(* Logix 5000 project; controller logix5561 vendor 1 type 14 code 54 rev 19.11; software revision 19.01 *)

TASK MainTask (continuous, watchdog 500 ms) : MainProgram

MODULES
   Local : vendor 1 type 14 code 54 (ICP 0, rev 19.11)
      EIP : 1756-ENBT (ICP 1, Ethernet 192.168.16.199, rev 6.1)
         Fuji_Inverter : ETHERNET-MODULE (Ethernet 192.168.16.28, rev 1.1, Output RPI 10 ms)
END_MODULES

ADD_ON_INSTRUCTION OPCE1WIE_Generic_Default_IO   (* revision 1.0 *)
// Simple interface for generic default IO mapping that uses Input Assembly Instance 150 and Output Assembly Instance 100.
VAR_IN_OUT
   I_Data : INT[2]; {required}   // Input data
   O_Data : INT[2]; {required}   // Output data
END_VAR
VAR_INPUT
   RunForward : BOOL; {access Read Only, required}   // Run Forward
   RunReverse : BOOL; {access Read Only, required}   // Run reverse
   ResetFault : BOOL; {access Read Only, required}   // Reset fault
   FrequencyCommand : INT; {access Read Only, required}   // Frequency command/reference
END_VAR
VAR_OUTPUT
   RunningForward : BOOL; {access Read Only, visible}   // Running forward
   RunningReverse : BOOL; {access Read Only, visible}   // Running reverse
   DCBreaking : BOOL; {access Read Only, visible}   // DC injection braking (or pre-exciting)
   InverterShutdown : BOOL; {access Read Only, visible}   // Inverter shutdown (stopped)
   Braking : BOOL; {access Read Only, visible}   // Braking
   DCBusVoltageNormal : BOOL; {access Read Only, visible}   // DC bus voltage normal
   TorqueLimiting : BOOL; {access Read Only, visible}   // Torque limited
   VoltageLimited : BOOL; {access Read Only, visible}   // Voltage limited
   CurrentLimited : BOOL; {access Read Only, visible}   // Current limited
   Accelerating : BOOL; {access Read Only, visible}   // Accelerating
   Decelerating : BOOL; {access Read Only, visible}   // Decelerating
   Alarm : BOOL; {access Read Only, visible}   // Alarm relay (for any fault)
   CommEstablished : BOOL; {access Read Only, visible}   // Communications established
   BusyWriting : BOOL; {access Read Only, visible}   // Write in progress
   OutputFrequency : INT; {access Read Only, visible}   // Output/feedback frequency
END_VAR

ROUTINE Logic   (* ladder *)
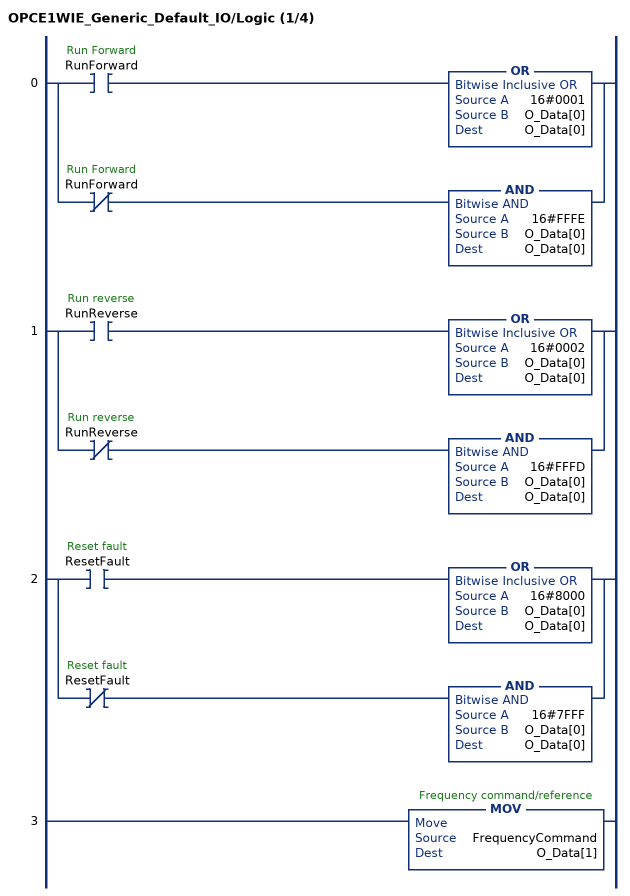
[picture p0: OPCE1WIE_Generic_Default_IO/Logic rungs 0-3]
   0: [XIC(RunForward) OR(16#0001,O_Data[0],O_Data[0]) ,XIO(RunForward) AND(16#FFFE,O_Data[0],O_Data[0]) ];
   1: [XIC(RunReverse) OR(16#0002,O_Data[0],O_Data[0]) ,XIO(RunReverse) AND(16#FFFD,O_Data[0],O_Data[0]) ];
   2: [XIC(ResetFault) OR(16#8000,O_Data[0],O_Data[0]) ,XIO(ResetFault) AND(16#7FFF,O_Data[0],O_Data[0]) ];
   3: MOV(FrequencyCommand,O_Data[1]);
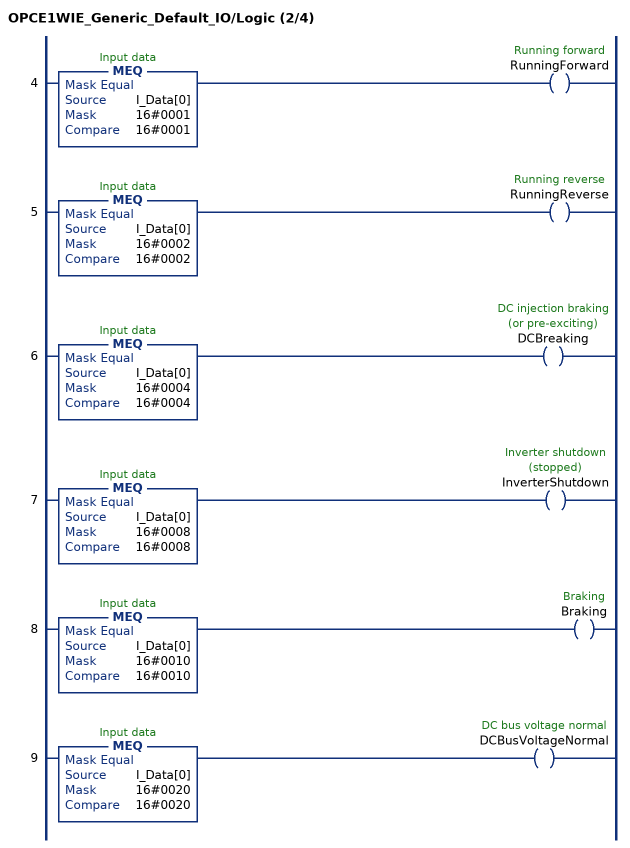
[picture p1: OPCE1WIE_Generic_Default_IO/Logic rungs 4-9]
   4: MEQ(I_Data[0],16#0001,16#0001)OTE(RunningForward);
   5: MEQ(I_Data[0],16#0002,16#0002)OTE(RunningReverse);
   6: MEQ(I_Data[0],16#0004,16#0004)OTE(DCBreaking);
   7: MEQ(I_Data[0],16#0008,16#0008)OTE(InverterShutdown);
   8: MEQ(I_Data[0],16#0010,16#0010)OTE(Braking);
   9: MEQ(I_Data[0],16#0020,16#0020)OTE(DCBusVoltageNormal);
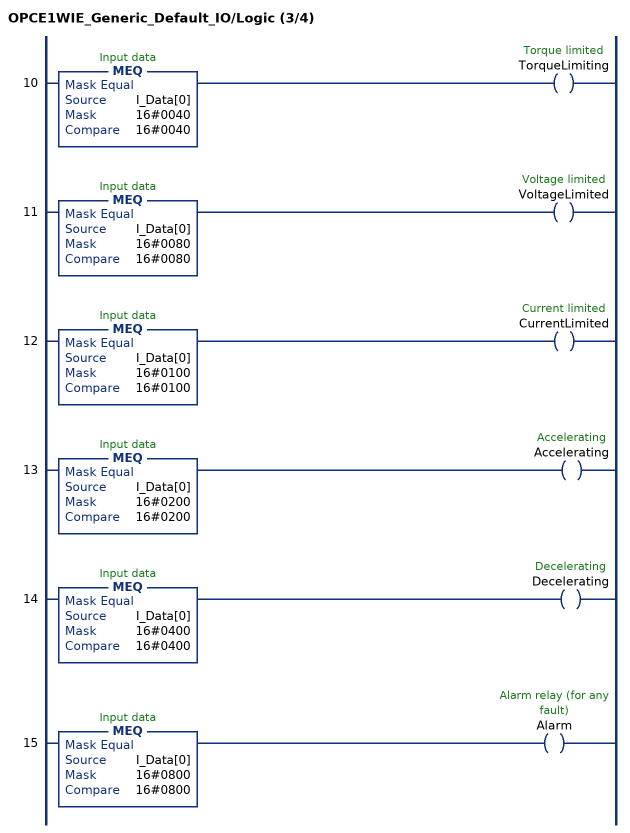
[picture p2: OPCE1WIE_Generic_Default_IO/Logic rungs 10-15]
   10: MEQ(I_Data[0],16#0040,16#0040)OTE(TorqueLimiting);
   11: MEQ(I_Data[0],16#0080,16#0080)OTE(VoltageLimited);
   12: MEQ(I_Data[0],16#0100,16#0100)OTE(CurrentLimited);
   13: MEQ(I_Data[0],16#0200,16#0200)OTE(Accelerating);
   14: MEQ(I_Data[0],16#0400,16#0400)OTE(Decelerating);
   15: MEQ(I_Data[0],16#0800,16#0800)OTE(Alarm);
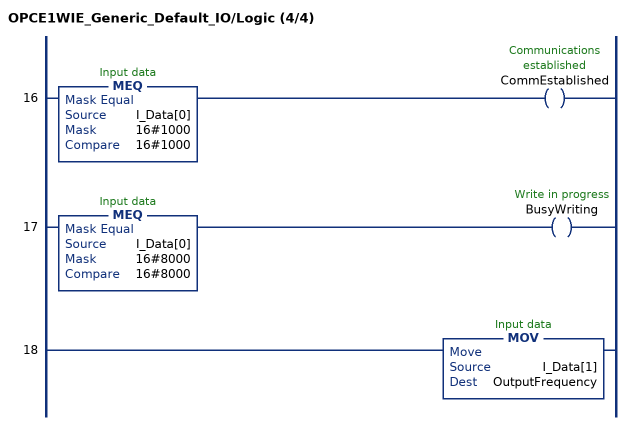
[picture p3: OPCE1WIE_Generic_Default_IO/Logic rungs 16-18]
   16: MEQ(I_Data[0],16#1000,16#1000)OTE(CommEstablished);
   17: MEQ(I_Data[0],16#8000,16#8000)OTE(BusyWriting);
   18: MOV(I_Data[1],OutputFrequency);
END_ROUTINE
END_ADD_ON_INSTRUCTION

VAR_GLOBAL   (* controller tags *)
   freq_cmd : INT;   // Frequency command
   generic_aoi : OPCE1WIE_Generic_Default_IO;
   reset : BOOL;   // Fault reset
   run_fwd : BOOL;   // Run forward direction
   run_rev : BOOL;   // Run reverse direction
END_VAR

PROGRAM MainProgram   (* main routine MainRoutine *)

ROUTINE MainRoutine   (* ladder *)
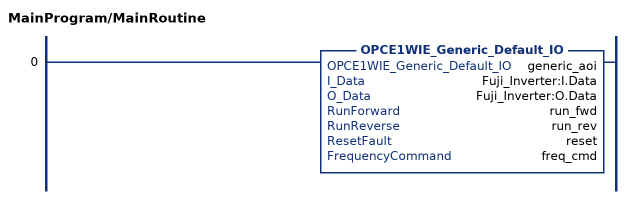
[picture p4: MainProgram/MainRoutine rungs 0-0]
   0: OPCE1WIE_Generic_Default_IO(generic_aoi,Fuji_Inverter:I.Data,Fuji_Inverter:O.Data,run_fwd,run_rev,reset,freq_cmd);
END_ROUTINE
END_PROGRAM
